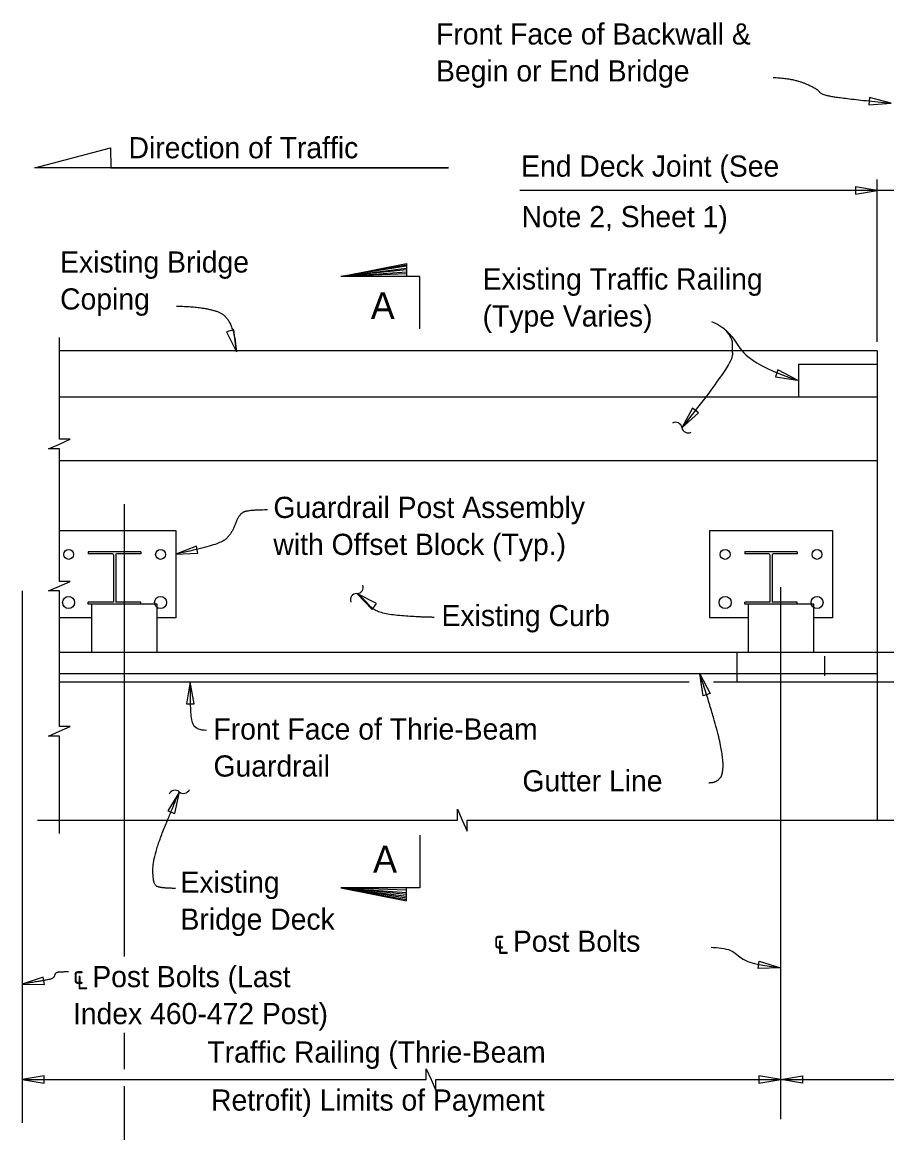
# Model space of a CAD drawing. Extents: x 21526.6 to 21595.9, y 56114.9 to 56157.2.
# Drawn here: x 21546.04 to 21554.27, y 56142.28 to 56152.85 of the extents above; entities that cross this region are included whole.
import ezdxf

# ---------------------------------------------------------------- set-up
doc = ezdxf.new("R2010")
doc.units = 0
for name, color, linetype in [('AdhocPoint_dp', 7, 'Continuous'), ('Border', 7, 'Continuous'), ('Patterning', 7, 'Continuous'), ('PlotBorder_dp', 7, 'Continuous'), ('TextMisc', 7, 'Continuous')]:
    doc.layers.add(name, color=color, linetype=linetype)

msp = doc.modelspace()

# ---------------------------------------------------------------- linework, layer by layer
at = {"layer": 'AdhocPoint_dp'}
for p, q in [((21554.182, 56149.72), (21546.396, 56149.72)), ((21554.182, 56149.722), (21554.182, 56145.254)), ((21553.432, 56149.595), (21554.182, 56149.595)), ((21546.396, 56149.282), (21554.182, 56149.282)), ((21546.396, 56148.678), (21554.182, 56148.678)), ((21546.395, 56146.648), (21554.182, 56146.648))]:
    msp.add_line(p, q, dxfattribs=at)
msp.add_lwpolyline([(21553.432, 56149.595), (21553.432, 56149.282)], dxfattribs=at)
at = {"layer": 'Patterning'}
for p, q in [((21547.015, 56143.955), (21547.015, 56148.26)), ((21546.042, 56147.435), (21546.042, 56142.373)), ((21552.848, 56146.57), (21552.848, 56146.851)), ((21552.848, 56146.851), (21566.396, 56146.851)), ((21553.682, 56146.628), (21553.682, 56146.813)), ((21552.848, 56146.57), (21566.234, 56146.57)), ((21547.015, 56142.884), (21547.015, 56143.228)), ((21547.015, 56136.022), (21547.015, 56142.721))]:
    msp.add_line(p, q, dxfattribs=at)
for points in [[(21546.703, 56147.309), (21546.703, 56146.851), (21547.328, 56146.851), (21547.328, 56147.309)], [(21552.953, 56147.309), (21552.953, 56146.851), (21553.578, 56146.851), (21553.578, 56147.309)]]:
    msp.add_lwpolyline(points, close=True, dxfattribs=at)
at = {"layer": 'PlotBorder_dp'}
for p, q in [((21546.162, 56151.463), (21546.884, 56151.655)), ((21546.884, 56151.655), (21546.886, 56151.463)), ((21549.973, 56151.463), (21546.162, 56151.463)), ((21546.886, 56151.463), (21550.099, 56151.463)), ((21550.099, 56151.463), (21549.973, 56151.463)), ((21554.182, 56149.808), (21554.182, 56151.352)), ((21554.69, 56151.248), (21550.781, 56151.248)), ((21549.076, 56150.429), (21549.701, 56150.539)), ((21549.701, 56150.526), (21549.076, 56150.429)), ((21549.076, 56150.429), (21549.701, 56150.509)), ((21549.701, 56150.491), (21549.076, 56150.429)), ((21549.076, 56150.429), (21549.701, 56150.473)), ((21549.701, 56150.453), (21549.076, 56150.429)), ((21553.263, 56142.407), (21553.263, 56147.47)), ((21549.701, 56144.586), (21549.076, 56144.609)), ((21549.076, 56144.609), (21549.701, 56144.566)), ((21549.701, 56144.547), (21549.076, 56144.609)), ((21549.076, 56144.609), (21549.701, 56144.529)), ((21549.701, 56144.512), (21549.076, 56144.609)), ((21549.076, 56144.609), (21549.701, 56144.499))]:
    msp.add_line(p, q, dxfattribs=at)
for points in [[(21554.314, 56152.078), (21554.11, 56152.134), (21554.103, 56152.064)], [(21554.182, 56151.248), (21553.974, 56151.283), (21553.974, 56151.212)], [(21548.081, 56149.712), (21548.056, 56149.922), (21547.988, 56149.902)], [(21553.424, 56149.441), (21553.237, 56149.539), (21553.215, 56149.472)], [(21552.322, 56148.989), (21552.479, 56149.131), (21552.424, 56149.175)], [(21547.504, 56147.786), (21547.715, 56147.794), (21547.701, 56147.863)], [(21549.228, 56147.411), (21549.373, 56147.258), (21549.416, 56147.315)], [(21552.493, 56146.647), (21552.591, 56146.46), (21552.524, 56146.438)], [(21547.642, 56146.569), (21547.607, 56146.36), (21547.678, 56146.36)], [(21547.539, 56145.523), (21547.429, 56145.343), (21547.494, 56145.317)], [(21553.26, 56143.847), (21553.048, 56143.841), (21553.058, 56143.911)], [(21546.042, 56143.693), (21546.253, 56143.69), (21546.242, 56143.76)], [(21546.042, 56142.784), (21546.25, 56142.748), (21546.25, 56142.819)], [(21553.263, 56142.784), (21553.054, 56142.819), (21553.054, 56142.748)], [(21553.263, 56142.784), (21553.471, 56142.819), (21553.471, 56142.748)]]:
    msp.add_lwpolyline(points, close=True, dxfattribs=at)
for points in [[(21549.826, 56149.929), (21549.826, 56150.429), (21549.076, 56150.429), (21549.701, 56150.554), (21549.701, 56150.429)], [(21546.396, 56148.32), (21546.396, 56148.789), (21546.292, 56148.789), (21546.396, 56148.834), (21546.499, 56148.879), (21546.396, 56148.879), (21546.396, 56149.848)], [(21546.396, 56146.573), (21546.396, 56147.436), (21546.292, 56147.436), (21546.396, 56147.481), (21546.499, 56147.526), (21546.396, 56147.526), (21546.396, 56148.32)], [(21546.396, 56145.126), (21546.396, 56146.054), (21546.292, 56146.054), (21546.396, 56146.099), (21546.499, 56146.144), (21546.396, 56146.144), (21546.396, 56147.017)], [(21546.187, 56145.254), (21550.187, 56145.254), (21550.187, 56145.357), (21550.232, 56145.254), (21550.277, 56145.15), (21550.277, 56145.254), (21554.19, 56145.254)], [(21554.182, 56145.254), (21556.177, 56145.254), (21556.177, 56145.357), (21556.222, 56145.254), (21556.267, 56145.15), (21556.267, 56145.254), (21558.132, 56145.254)], [(21549.826, 56145.109), (21549.826, 56144.609), (21549.076, 56144.609), (21549.701, 56144.484), (21549.701, 56144.609)], [(21546.042, 56142.784), (21549.889, 56142.784), (21549.889, 56142.887), (21549.934, 56142.784), (21549.979, 56142.68), (21549.979, 56142.784), (21562.023, 56142.784)]]:
    msp.add_lwpolyline(points, dxfattribs=at)
for centre, start, end in [((21552.263, 56148.981), 8.6098, 120.3371), ((21552.381, 56148.999), 188.6098, 300.3371), ((21549.228, 56147.47), 269.4704, 21.1976), ((21549.227, 56147.351), 89.4704, 201.1976), ((21547.578, 56145.567), 227.1839, 338.9112), ((21547.497, 56145.479), 47.1839, 158.9112)]:
    msp.add_arc(centre, 0.0596, start, end, dxfattribs=at)
for points, degree in [([(21553.192, 56152.323), (21553.377, 56152.316), (21553.614, 56152.217), (21553.647, 56152.158), (21553.918, 56152.118), (21554.314, 56152.078)], 2), ([(21547.51, 56150.146), (21547.749, 56150.146), (21548.058, 56150.042), (21548.081, 56149.712)], 2), ([(21552.604, 56149.999), (21552.681, 56149.974), (21552.84, 56149.858), (21552.933, 56149.6), (21553.424, 56149.441)], 3), ([(21552.719, 56149.939), (21552.802, 56149.846), (21552.802, 56149.749), (21552.802, 56149.595), (21552.322, 56148.989)], 2), ([(21548.378, 56148.206), (21548.195, 56148.206), (21548.103, 56148.165), (21548.033, 56147.966), (21547.894, 56147.867), (21547.504, 56147.786)], 2), ([(21549.965, 56147.184), (21549.833, 56147.184), (21549.409, 56147.22), (21549.294, 56147.362), (21549.228, 56147.411)], 2), ([(21552.578, 56145.61), (21552.674, 56145.61), (21552.73, 56145.755), (21552.661, 56146.134), (21552.493, 56146.647)], 2), ([(21547.797, 56146.107), (21547.731, 56146.11), (21547.667, 56146.137), (21547.642, 56146.231), (21547.642, 56146.569)], 3), ([(21547.501, 56144.604), (21547.349, 56144.604), (21547.286, 56144.65), (21547.286, 56144.908), (21547.494, 56145.424), (21547.539, 56145.523)], 2), ([(21552.6, 56144.043), (21552.664, 56144.041), (21552.808, 56144.028), (21552.884, 56143.922), (21553.025, 56143.88), (21553.26, 56143.847)], 3), ([(21546.484, 56143.809), (21546.418, 56143.808), (21546.354, 56143.802), (21546.345, 56143.745), (21546.219, 56143.721), (21546.042, 56143.693)], 2)]:
    msp.add_open_spline(points, degree=degree, dxfattribs=at)
at = {"layer": 'TextMisc'}
for p, q in [((21547.171, 56147.809), (21546.671, 56147.809)), ((21546.671, 56147.809), (21546.671, 56147.788)), ((21546.9, 56147.788), (21546.671, 56147.788)), ((21546.911, 56147.778), (21546.911, 56147.33)), ((21546.932, 56147.778), (21546.932, 56147.33)), ((21547.171, 56147.788), (21546.942, 56147.788)), ((21547.171, 56147.809), (21547.171, 56147.788)), ((21553.421, 56147.809), (21552.921, 56147.809)), ((21552.921, 56147.809), (21552.921, 56147.788)), ((21553.15, 56147.788), (21552.921, 56147.788)), ((21553.161, 56147.778), (21553.161, 56147.33)), ((21553.182, 56147.778), (21553.182, 56147.33)), ((21553.421, 56147.788), (21553.192, 56147.788)), ((21553.421, 56147.809), (21553.421, 56147.788)), ((21546.911, 56147.33), (21546.671, 56147.33)), ((21546.671, 56147.309), (21546.671, 56147.33)), ((21547.171, 56147.309), (21546.671, 56147.309)), ((21547.171, 56147.33), (21546.932, 56147.33)), ((21547.171, 56147.309), (21547.171, 56147.33)), ((21553.161, 56147.33), (21552.921, 56147.33)), ((21552.921, 56147.309), (21552.921, 56147.33)), ((21553.421, 56147.309), (21552.921, 56147.309)), ((21553.421, 56147.33), (21553.182, 56147.33)), ((21553.421, 56147.309), (21553.421, 56147.33)), ((21546.395, 56146.851), (21552.848, 56146.851)), ((21546.395, 56146.57), (21552.393, 56146.57)), ((21552.624, 56146.57), (21552.848, 56146.57))]:
    msp.add_line(p, q, dxfattribs=at)
for points in [[(21546.396, 56148.012), (21547.505, 56148.012), (21547.505, 56147.179), (21547.328, 56147.179)], [(21552.953, 56147.179), (21552.588, 56147.179), (21552.588, 56148.012), (21553.755, 56148.012), (21553.755, 56147.179), (21553.578, 56147.179)], [(21546.703, 56147.179), (21546.396, 56147.179)]]:
    msp.add_lwpolyline(points, dxfattribs=at)
for centre, radius in [((21546.484, 56147.783), 0.0469), ((21547.359, 56147.783), 0.0469), ((21552.734, 56147.783), 0.0469), ((21553.609, 56147.783), 0.0469), ((21546.484, 56147.325), 0.0573), ((21547.359, 56147.325), 0.0573), ((21552.734, 56147.325), 0.0573), ((21553.609, 56147.325), 0.0573)]:
    msp.add_circle(centre, radius, dxfattribs=at)
for centre, start, end in [((21546.9, 56147.778), 0, 90), ((21546.942, 56147.778), 90, 180), ((21553.15, 56147.778), 0, 90), ((21553.192, 56147.778), 90, 180)]:
    msp.add_arc(centre, 0.0104, start, end, dxfattribs=at)

# ---------------------------------------------------------------- texts
at = {"layer": 'Border'}
msp.add_text('Direction of Traffic', height=0.2016, rotation=359.9998, dxfattribs=at).set_placement((21547.054, 56151.554))
for s, height, p in [('End Deck Joint (See', 0.2016, (21550.792, 56151.379)), ('Note 2, Sheet 1)', 0.2016, (21550.796, 56150.898)), ('A', 0.256, (21549.36, 56150.023)), ('Existing Curb', 0.2016, (21550.034, 56147.1)), ('Gutter Line', 0.2016, (21550.804, 56145.527)), ('A', 0.256, (21549.382, 56144.754)), ('℄ Post Bolts', 0.2016, (21550.529, 56144))]:
    msp.add_text(s, height=height, dxfattribs=at).set_placement(p)
at = {"layer": 'PlotBorder_dp'}
for s, p in [('Front Face of Backwall &', (21549.982, 56152.637)), ('Begin or End Bridge', (21549.982, 56152.285)), ('Existing Bridge ', (21546.403, 56150.466)), ('Existing Traffic Railing', (21550.425, 56150.304)), ('Coping ', (21546.403, 56150.114)), ('(Type Varies)', (21550.425, 56149.952)), ('Guardrail Post Assembly ', (21548.433, 56148.13)), ('with Offset Block (Typ.)', (21548.433, 56147.778)), ('Front Face of Thrie-Beam ', (21547.863, 56146.02)), ('Guardrail', (21547.863, 56145.668)), ('Existing ', (21547.549, 56144.562)), ('Bridge Deck', (21547.549, 56144.21)), ('℄ Post Bolts (Last', (21546.525, 56143.663)), ('Index 460-472 Post)', (21546.525, 56143.311)), ('Traffic Railing (Thrie-Beam ', (21547.805, 56142.945)), ('Retrofit) Limits of Payment', (21547.84, 56142.488))]:
    msp.add_text(s, height=0.2016, dxfattribs=at).set_placement(p)

doc.saveas('drawing.dxf')
